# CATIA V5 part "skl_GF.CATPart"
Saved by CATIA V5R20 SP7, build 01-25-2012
Part number: skl_GF
Bounding box of the stored display mesh (mm): x -20 to 0, y 83.1 to 124.167, z 0 to 63.473
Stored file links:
  U:\IAO-Thinkmotion\TRAVAIL A RENDRE\skl_GF.CATPart
  U:\IAO-Thinkmotion\TRAVAIL A RENDRE\skl_FE.CATPart
  U:\IAO-Thinkmotion\TRAVAIL A RENDRE\skl_levier2bras.CATProduct
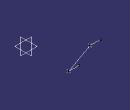
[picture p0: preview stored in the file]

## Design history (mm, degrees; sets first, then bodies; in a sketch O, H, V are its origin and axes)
Set1
  DatumPoint1 "Point F": linked copy from another document
  Point1 "Point G": linked copy from another document
  Plane1: linked copy from another document
Set2
  Line1 "FG": type PtPt, FirstPoint DatumPoint1, SecondPoint Point1
  Line2 "Axe_FG_F": type Normal, RefPoint DatumPoint1, RefSkin Plane1, Start 0, End 20
  Line3 "Axe_FG_G": type Normal, RefPoint Point1, RefSkin Plane1, Start 0, End 20
Body1 (main body)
